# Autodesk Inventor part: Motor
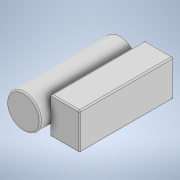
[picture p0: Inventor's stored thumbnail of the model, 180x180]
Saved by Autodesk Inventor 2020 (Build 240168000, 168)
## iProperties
Created: 2019-06
Part Number: Motor
Material: Generic
Document SubType Name: Modeling
Designer: cl
Density: 1 g/cm^3
Appearance: Default
Author: cl
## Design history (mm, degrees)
sketch "Sketch1"
  geometry: C1 r 65 at (0, 0); 1 further point
  constraints: 1 centre point, 1 coincident
  dimensions: "d0" = 130 diameter of C1
extrude "Extrusion1" new body sketch "Sketch1" distance "d1" = 370; taper "d2" = 0 deg
workplane "Work Plane1"
sketch "Sketch2"
  geometry: L1 (65, 70)-(175, 70); L2 (175, 70)-(175, -70); L3 (175, -70)-(65, -70); L4 (65, -70)-(65, 70); L5 (-65, 0)-(65, 0); L6 (65, 0)-(231.584, 0); C1 r 65 at (0, 0) reference; A1 r 65 centre (0, 0) between (-65, 0) and (65, 0) reference; 1 further point
  constraints: 12 end point, 2 horizontal, 2 parallel, 2 point on circle, 1 midpoint, 1 perpendicular, 1 point on line, 1 tangent
  dimensions: "d4" = 110 distance of L2.end L3.end; "d5" = 140 distance of L1.end L2.end; "d6" = 70 distance between parallel lines of L1 L6
extrude "Extrusion2" join sketch "Sketch2" distance "d7" = 360; taper "d8" = 0 deg
fillet "Fillet6" dims "d14" = 5
fillet "Fillet7" dims "d15" = 5
body "Solid1"
